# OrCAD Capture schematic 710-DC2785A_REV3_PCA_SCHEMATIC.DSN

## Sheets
1 PAGE3: size A
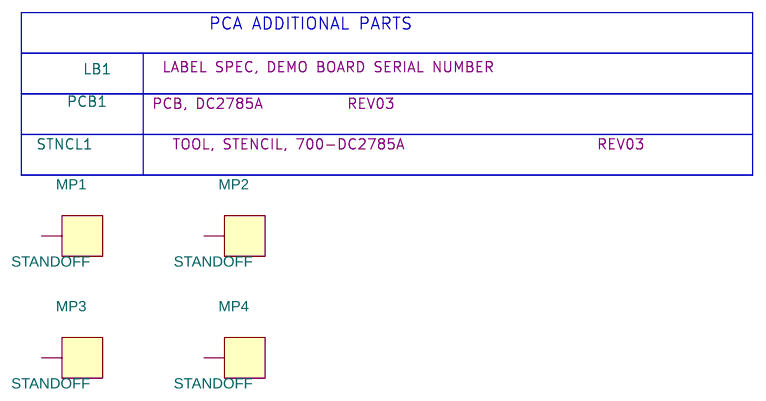
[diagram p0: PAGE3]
2 PAGE1: size Custom; company: ANALOG DEVICES INC.; note: DEMO BOARD BILL OF MATERIALS; note: TINY QUAD STEP-DOWN     MODULE     REGULATOR
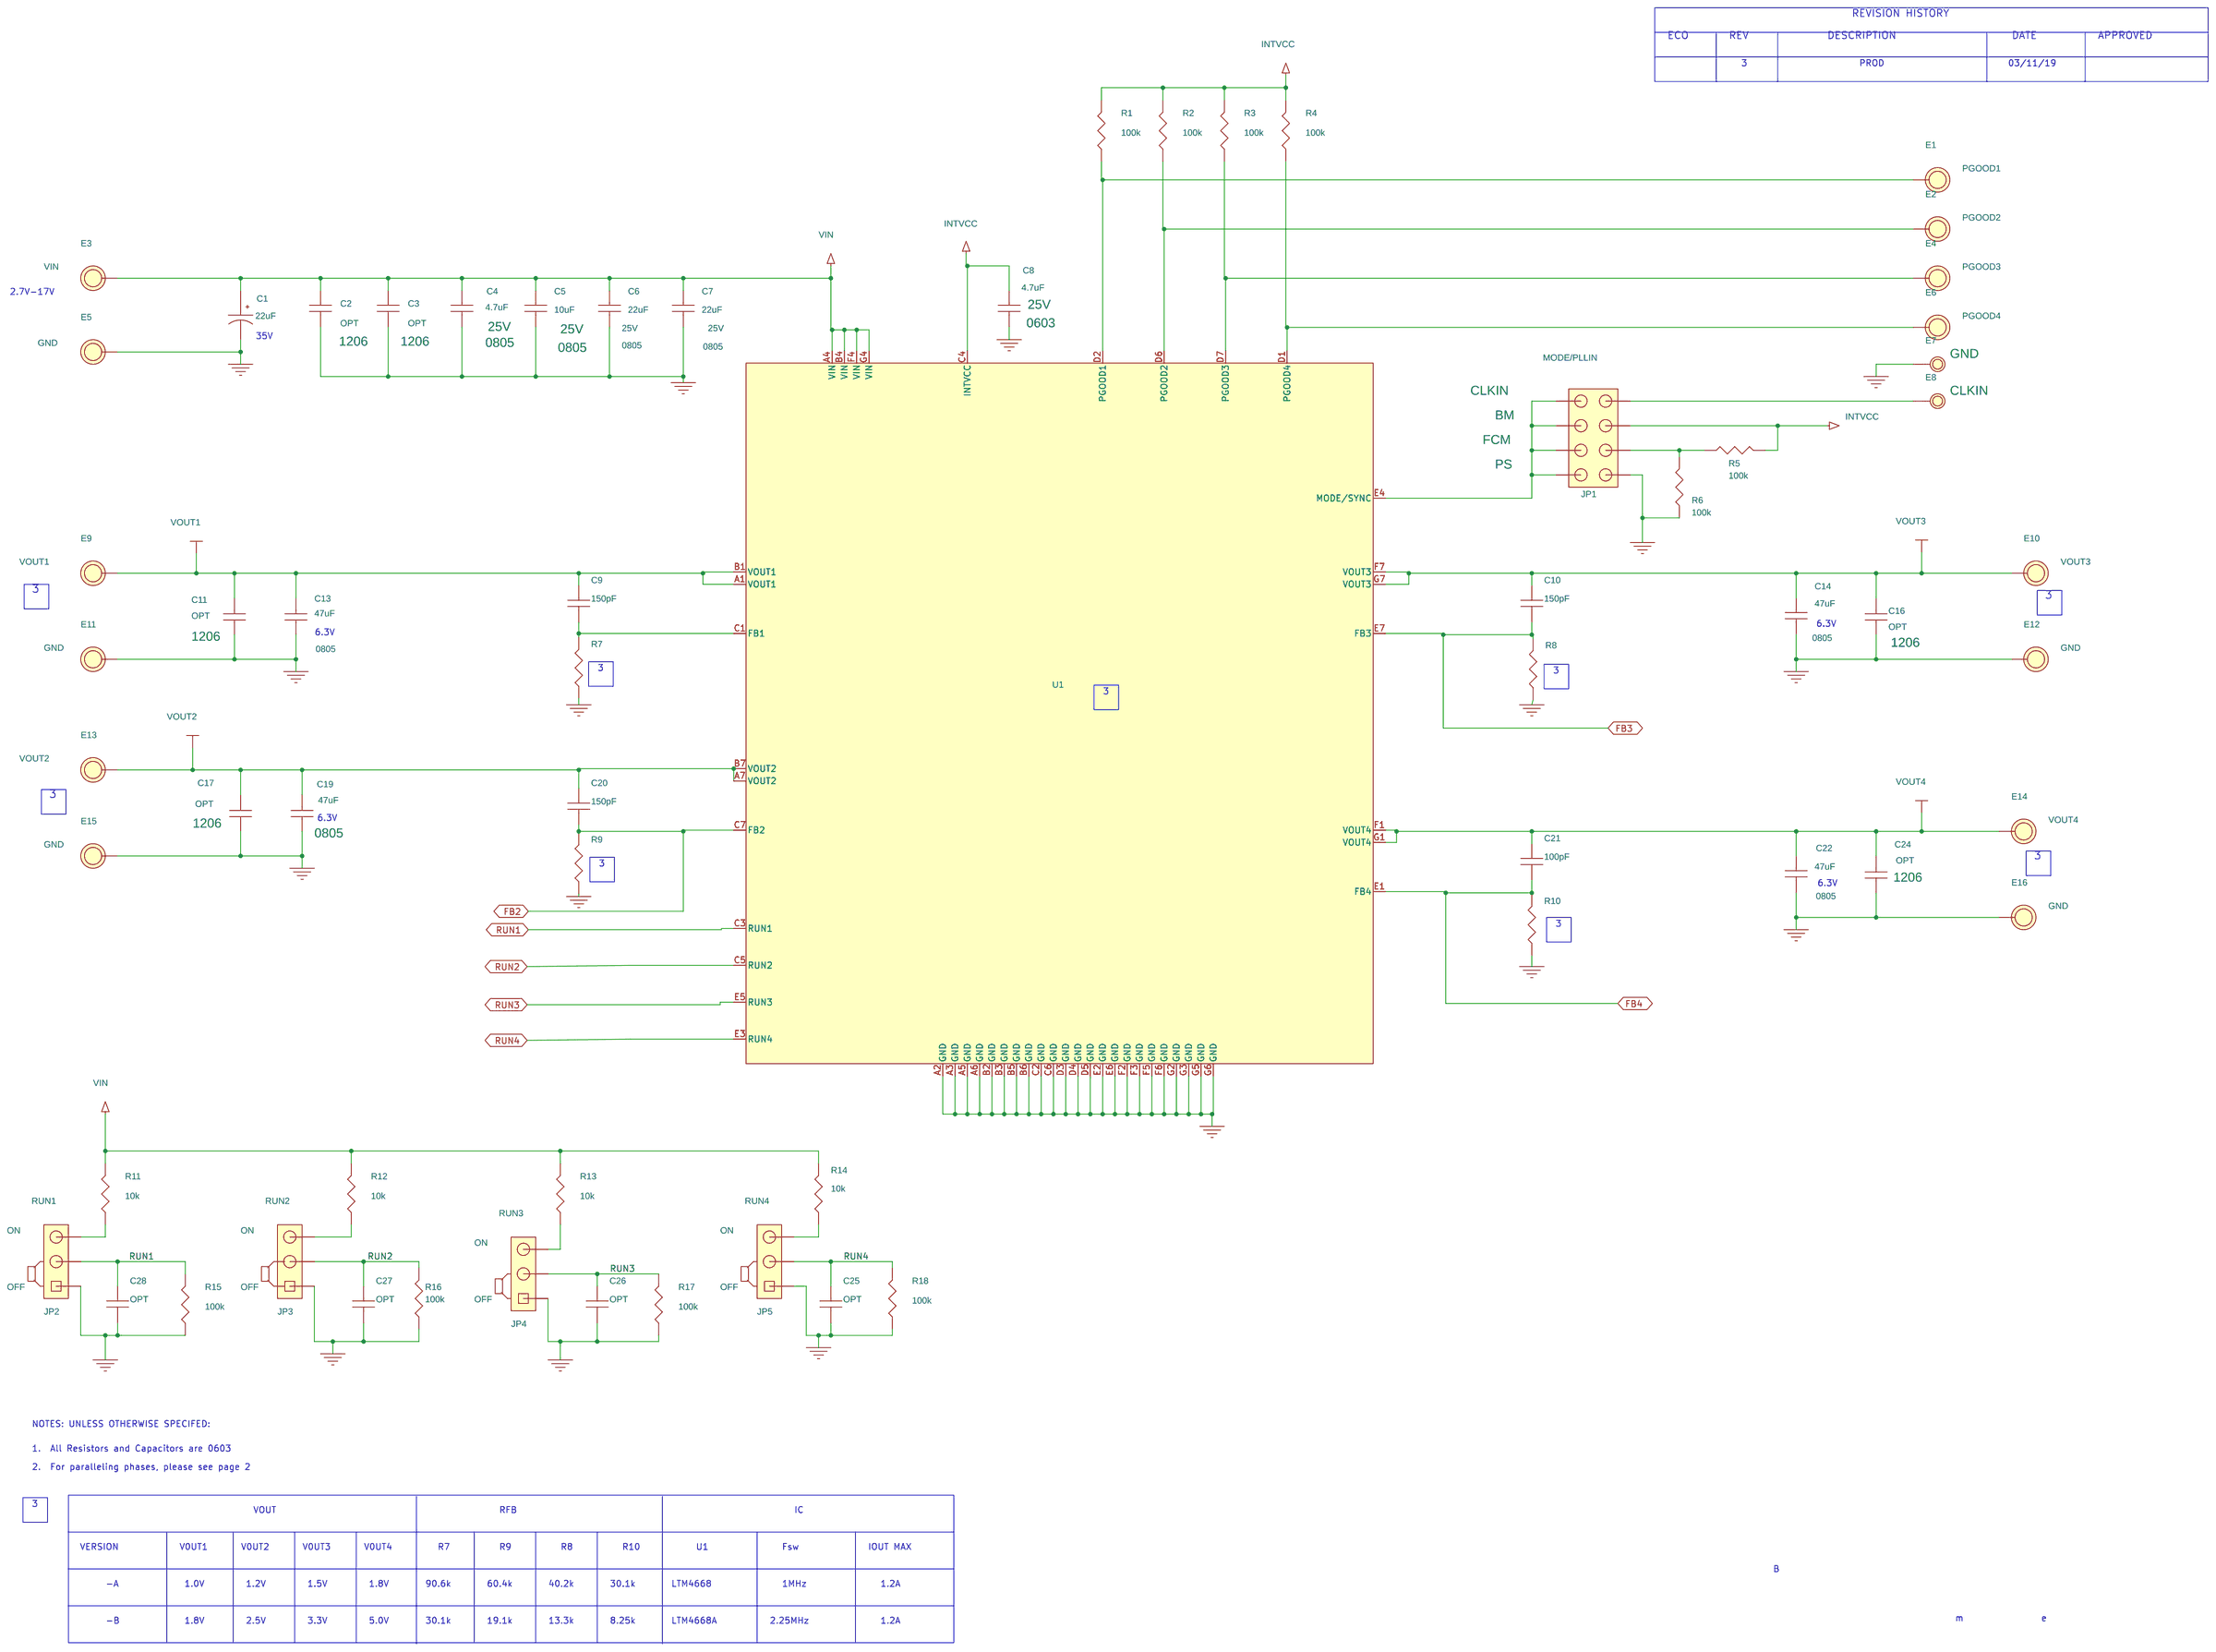
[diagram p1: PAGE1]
3 PAGE2: size Custom; company: ANALOG DEVICES INC.; note: DEMO BOARD BILL OF MATERIALS; note: TINY QUAD STEP-DOWN     MODULE     REGULATOR
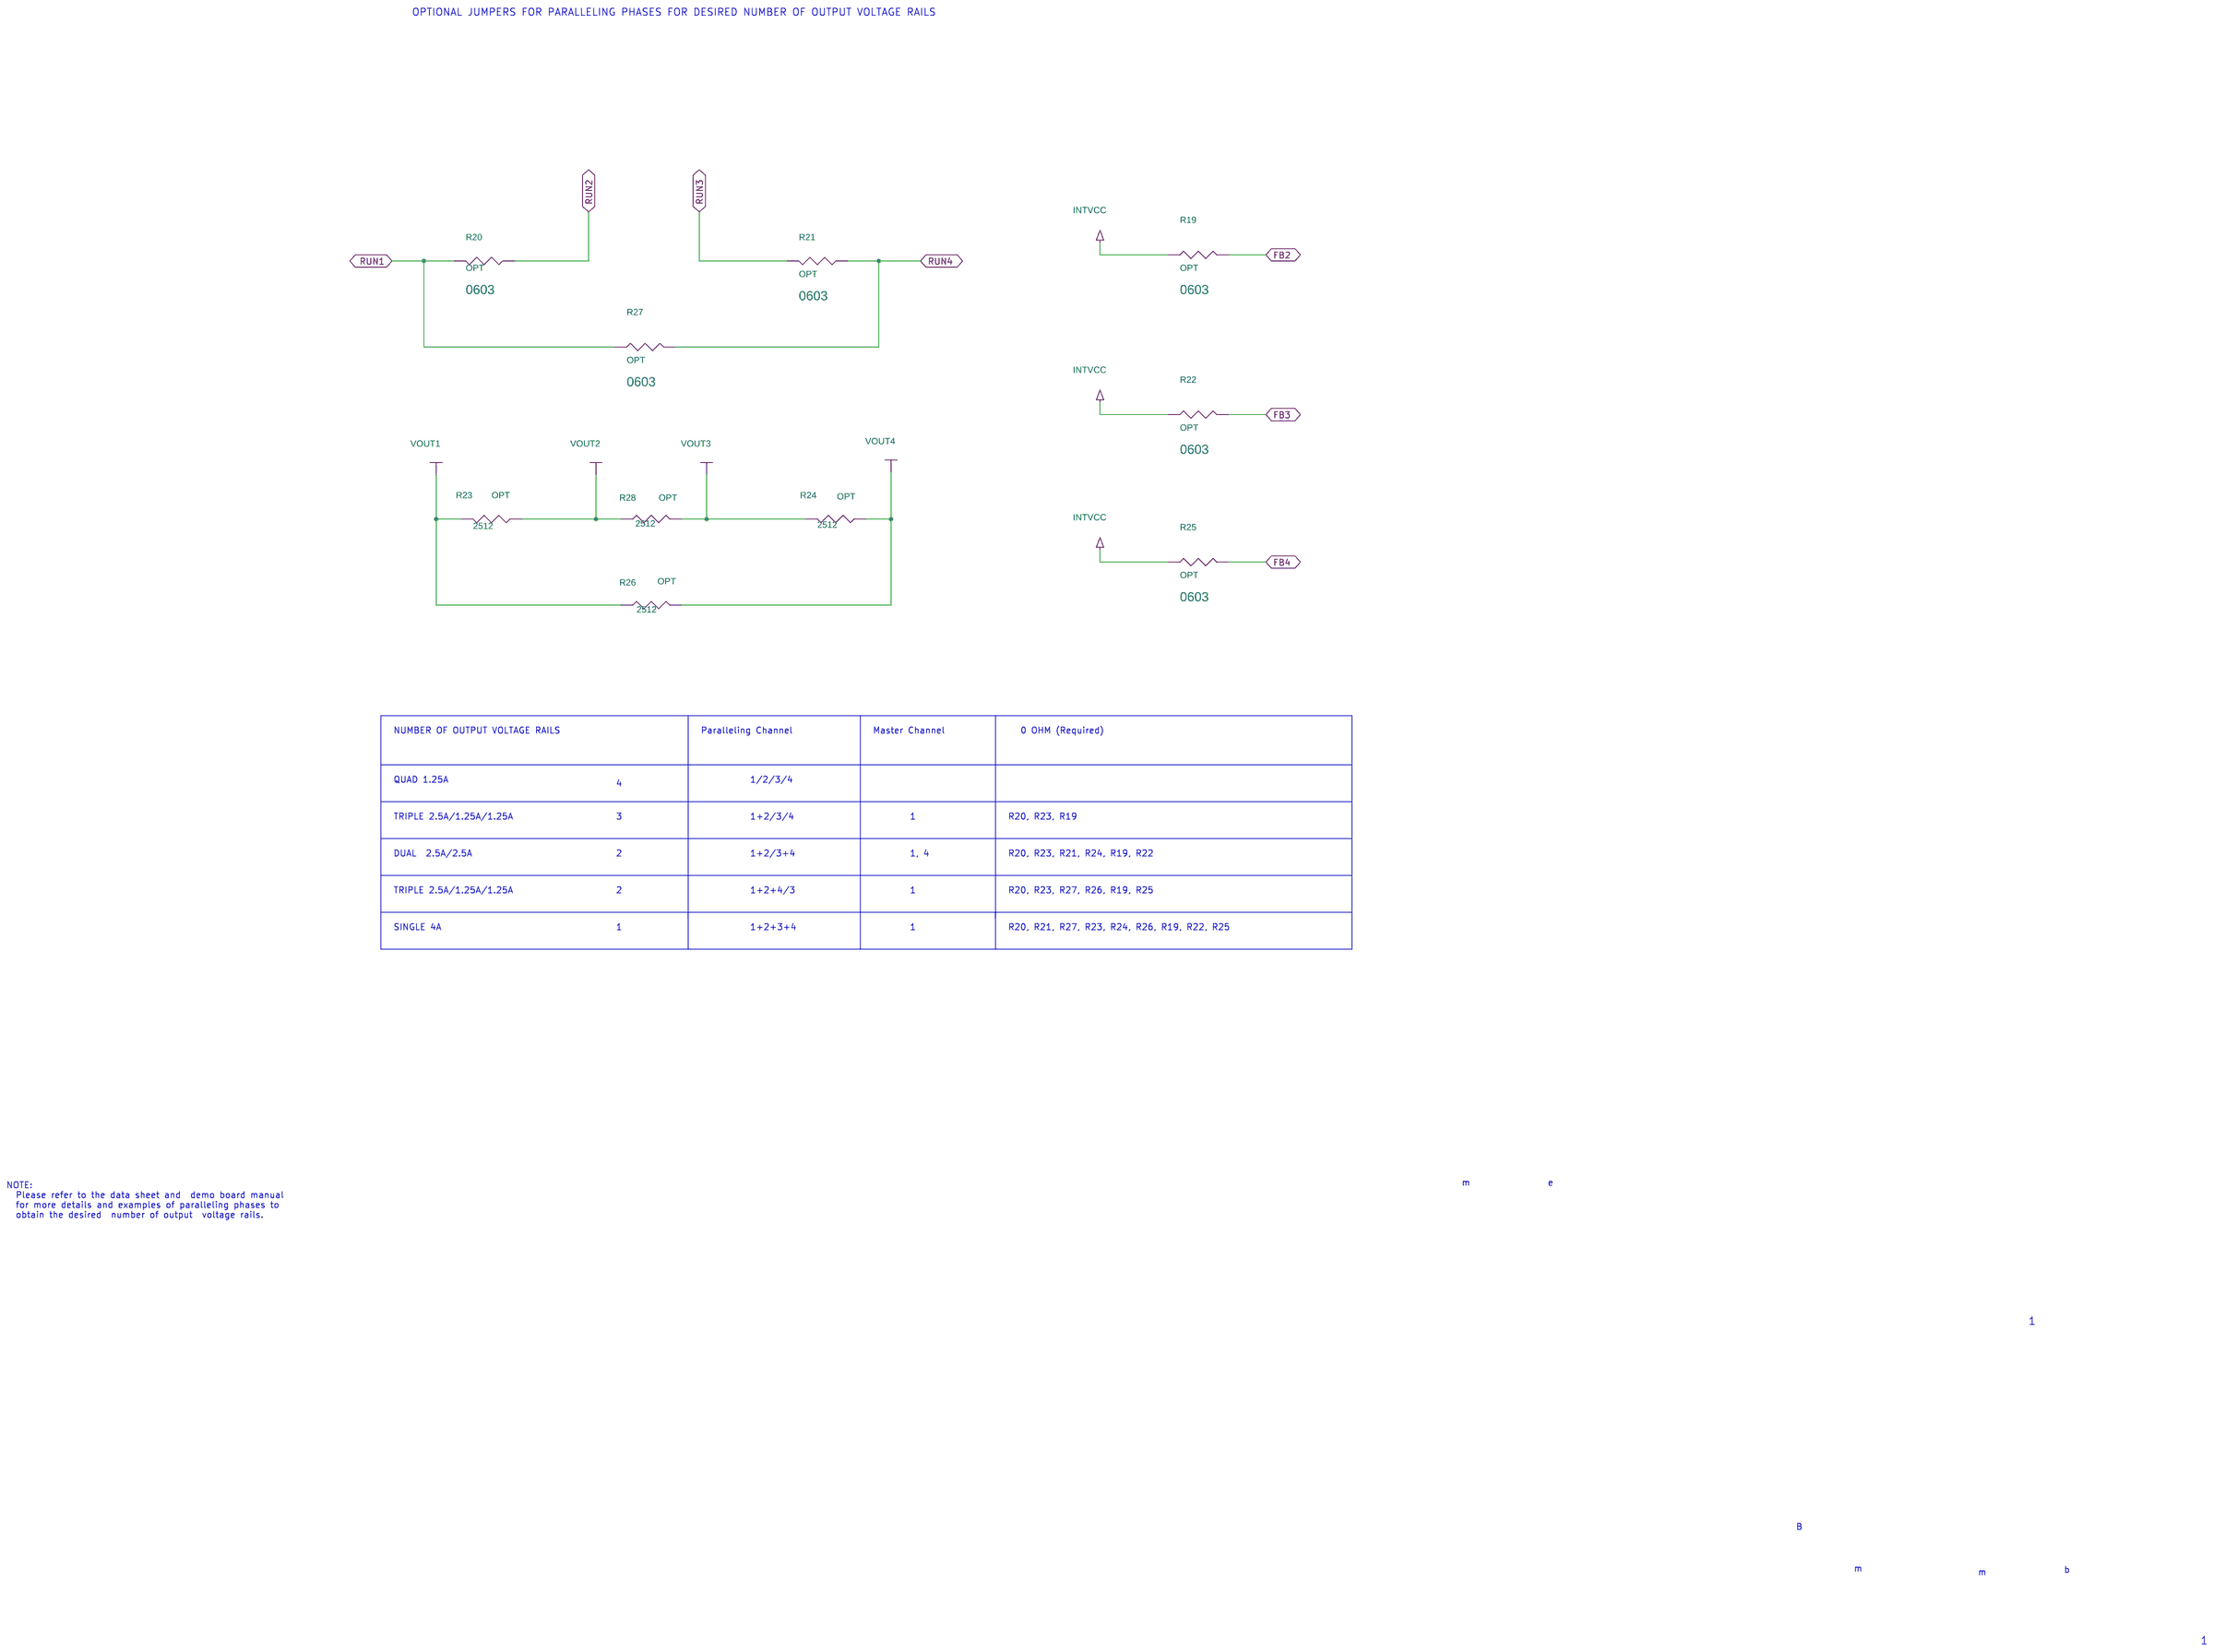
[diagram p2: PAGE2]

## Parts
sheet PAGE1
C1  22uF  [CAPMP7343N]
C2  OPT  [CC1206N]
C3  OPT  [CC1206N]
C4  4.7uF  [CC0805N]
C5  10uF  [CC0805N]
C6  22uF  [CC0805N]
C7  22uF  [CC0805N]
C8  4.7uF  [CC0603N]
C9  150pF  [CC0603N]
C10  150pF  [CC0603N]
C11  OPT  [CC1206N]
C13  47uF  [CC0805N]
C14  47uF  [CC0805N]
C16  OPT  [CC1206N]
C17  OPT  [CC1206N]
C19  47uF  [CC0805N]
C20  150pF  [CC0603N]
C21  100pF  [CC0603N]
C22  47uF  [CC0805N]
C24  OPT  [CC1206N]
C25  OPT  [CC0603N]
C26  OPT  [CC0603N]
C27  OPT  [CC0603N]
C28  OPT  [CC0603N]
E1  TEST POINT  [MILLMAX2501]
E2  TEST POINT  [MILLMAX2501]
E3  TEST POINT  [MILLMAX2501]
E4  TEST POINT  [MILLMAX2501]
E5  TEST POINT  [MILLMAX2501]
E6  TEST POINT  [MILLMAX2501]
E7  TEST POINT  [MILLMAX2308]
E8  TEST POINT  [MILLMAX2308]
E9  TEST POINT  [MILLMAX2501]
E10  TEST POINT  [MILLMAX2501]
E11  TEST POINT  [MILLMAX2501]
E12  TEST POINT  [MILLMAX2501]
E13  TEST POINT  [MILLMAX2501]
E14  TEST POINT  [MILLMAX2501]
E15  TEST POINT  [MILLMAX2501]
E16  TEST POINT  [MILLMAX2501]
JP1  HDR  [HD2X4-079]
JP2  HDR  [HD1X3-079]
JP3  HDR  [HD1X3-079]
JP4  HDR  [HD1X3-079]
JP5  HDR  [HD1X3-079]
R1  100k  [CR0603N]
R2  100k  [CR0603N]
R3  100k  [CR0603N]
R4  100k  [CR0603N]
R5  100k  [CR0603N]
R6  100k  [CR0603N]
R7  60.4k  [CR0603N]
R8  30.1k  [CR0603N]
R9  40.2k  [CR0603N]
R10  19.1k  [CR0603N]
R11  10k  [CR0603N]
R12  10k  [CR0603N]
R13  10k  [CR0603N]
R14  10k  [CR0603N]
R15  100k  [CR0603N]
R16  100k  [CR0603N]
R17  100k  [CR0603N]
R18  100k  [CR0603N]
U1  LTM4668-BGA  [LTC-BGA-49-1518]
XJP1  SHUNT
XJP2  SHUNT
XJP3  SHUNT
XJP4  SHUNT
XJP5  SHUNT
sheet PAGE2
R19  OPT  [CR0603N]
R20  OPT  [CR0603N]
R21  OPT  [CR0603N]
R22  OPT  [CR0603N]
R23  OPT  [CR2512N]
R24  OPT  [CR2512N]
R25  OPT  [CR0603N]
R26  OPT  [CR2512N]
R27  OPT  [CR0603N]
R28  OPT  [CR2512N]
sheet PAGE3
LB1  LABEL  [895-0154_REV01]
MP1  STANDOFF  [KEYSTONE_8829-8834]
MP2  STANDOFF  [KEYSTONE_8829-8834]
MP3  STANDOFF  [KEYSTONE_8829-8834]
MP4  STANDOFF  [KEYSTONE_8829-8834]
PCB1  PCB, DC2785A
STNCL1  TOOL, STENCIL, 700-DC2785A

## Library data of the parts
C1 = CAP_P: CAP.,22uF,TANT.,35V,20%,7343,TPSE, NO SUBS. ALLOWED; CLASS: DISCRETE; Dielectric Type: TANT.; FPLIST: CAPMP7343N,CAMP7343L,CAMP7343M; Manufacturer: AVX; Manufacturer PN: TPSE226M035R0125; PART_NUMBER: 150-0636; Package Size: 7343; Package Type: Surface Mount; Part Number: AVX TPSE226M035R0125; Rated Voltage: 35V; Tolerance: 20%; UserField01: NO SUB ALLOW
C2 C3 C11 C17 C24 = CAP: CAP., OPTION, 1206; CLASS: DISCRETE; FPLIST: CC1206N,CC1206L,CC1206M; PART_NUMBER: 150-3160; Package Size: 1206; Package Type: SMD; Part Number: OPTION
C4 = CAP: CAP.,4.7uF,X7R,25V,10%,0805; CLASS: DISCRETE; Dielectric Type: X7R; FPLIST: CC0805N,CC0805L,CC0805M; Manufacturer: MURATA; Manufacturer PN: GRM21BR71E475KA73L; PART_NUMBER: 150-3337; Package Size: 0805; Part Number: MURATA GRM21BR71E475KA73L; Rated Voltage: 25V; Tolerance: 10%
C5 = CAP: CAP.,10uF,X5R,25V,10%,0805; CLASS: DISCRETE; Dielectric Type: X5R; FPLIST: CC0805N,CC0805L,CC0805M; Manufacturer: MURATA; Manufacturer PN: GRM219R61E106KA12D; PART_NUMBER: 150-3455; Package Size: 0805; Part Number: MURATA GRM219R61E106KA12D; Rated Voltage: 25V; Tolerance: 10%; UserField01: Thickness = 0.85 +/-0.1mm
C6 C7 = CAP: CAP.,22uF,X5R,25V,20%,0805; CLASS: DISCRETE; Dielectric Type: X5R; FPLIST: CC0805N,CC0805L,CC0805M; Manufacturer: MURATA; Manufacturer PN: GRM21BR61E226ME44L; PART_NUMBER: 150-0387; Package Size: 0805; Part Number: MURATA GRM21BR61E226ME44L; Rated Voltage: 25V; Tolerance: 20%
C8 = CAP: CAP.,4.7uF,X5R,25V,20%,0603; 1ST PART FIELD: 25V; CLASS: DISCRETE; Dielectric Type: X5R; FPLIST: CC0603N,CC0603L,CC0603M; Manufacturer: TDK; Manufacturer PN: C1608X5R1E475M080AC; PART_NUMBER: 150-2378; Package Size: 0603; Part Number: TDK C1608X5R1E475M080AC; Rated Voltage: 25V; Tolerance: 20%
C9 C10 C20 = CAP: CAP.,150pF,NP0,50V,5%,0603; 1ST PART FIELD: 25V; 2ND PART FIELD: 0805-1206; CLASS: DISCRETE; Dielectric Type: NP0; FPLIST: CC0603N,CC0603L,CC0603M; Manufacturer: AVX; Manufacturer PN: 06035A151JAT2A; PART_NUMBER: 150-2306; Package Size: 0603; Part Number: AVX 06035A151JAT2A; Rated Voltage: 50V; Tolerance: 5%
C13 C14 C19 C22 = CAP: CAP.,47uF,X5R,6.3V,20%,0805; 1ST PART FIELD: 6.3V; CLASS: DISCRETE; Dielectric Type: X5R; FPLIST: CC0805N,CC0805L,CC0805M; Inventory Qty: 15642; Manufacturer: MURATA; Manufacturer PN: GRM21BR60J476ME15L; PART_NUMBER: 150-0140; Package Size: 0805; Part Number: TDK C3216X5R1C476M160AB; Rated Voltage: 6.3V; Tolerance: 20%
C16 = CAP: CAP., OPTION, 1206; 1ST PART FIELD: 25V; 2ND PART FIELD: 0805-1206; CLASS: DISCRETE; PART_NUMBER: 150-3160; Package Size: 1206; Package Type: SMD; Part Number: OPTION
C21 = CAP: CAP.,100pF,C0G,50V,5%,0603,AEC-Q200; 1ST PART FIELD: 25V; 2ND PART FIELD: 0805-1206; CLASS: DISCRETE; Dielectric Type: C0G; FPLIST: CC0603N,CC0603L,CC0603M; Manufacturer: TDK; Manufacturer PN: CGA3E2C0G1H101J080AA; PART_NUMBER: 150-0516; Package Size: 0603; Part Number: TDK CGA3E2C0G1H101J080AA; Rated Voltage: 50V; Tolerance: 5%; UserField01: AEC-Q200
C25-C28 = CAP: CAP., OPTION, 0603; 1ST PART FIELD: 25V; 2ND PART FIELD: 0805-1206; CLASS: DISCRETE; FPLIST: CC0603N,CC0603L,CC0603M; PART_NUMBER: 150-3038; Package Size: 0603; Package Type: SMD; Part Number: OPTION; UserField01: OPTION
E1 = TURRET_A: TEST POINT,TURRET,0.094",MTG. HOLE; CLASS: IO; FPLIST: MILLMAX2501,MILLMAX2501_ALT1; Manufacturer: MILL-MAX; Manufacturer PN: 2501-2-00-80-00-00-07-0; PART_FIELD_01: PGOOD1; PART_NUMBER: 260-0003; Part Number: MILL-MAX 2501-2-00-80-00-00-07-0
E2 = TURRET_A: TEST POINT,TURRET,0.094",MTG. HOLE; CLASS: IO; FPLIST: MILLMAX2501,MILLMAX2501_ALT1; Manufacturer: MILL-MAX; Manufacturer PN: 2501-2-00-80-00-00-07-0; PART_FIELD_01: PGOOD2; PART_NUMBER: 260-0003; Part Number: MILL-MAX 2501-2-00-80-00-00-07-0
E3 = TURRET_A: TEST POINT,TURRET,0.094",MTG. HOLE; CLASS: IO; FPLIST: MILLMAX2501,MILLMAX2501_ALT1; Manufacturer: MILL-MAX; Manufacturer PN: 2501-2-00-80-00-00-07-0; PART_FIELD_01: VIN; PART_NUMBER: 260-0003; Part Number: MILL-MAX 2501-2-00-80-00-00-07-0
E4 = TURRET_A: TEST POINT,TURRET,0.094",MTG. HOLE; CLASS: IO; FPLIST: MILLMAX2501,MILLMAX2501_ALT1; Manufacturer: MILL-MAX; Manufacturer PN: 2501-2-00-80-00-00-07-0; PART_FIELD_01: PGOOD3; PART_NUMBER: 260-0003; Part Number: MILL-MAX 2501-2-00-80-00-00-07-0
E5 E11 E12 E15 E16 = TURRET_A: TEST POINT,TURRET,0.094",MTG. HOLE; CLASS: IO; FPLIST: MILLMAX2501,MILLMAX2501_ALT1; Manufacturer: MILL-MAX; Manufacturer PN: 2501-2-00-80-00-00-07-0; PART_FIELD_01: GND; PART_NUMBER: 260-0003; Part Number: MILL-MAX 2501-2-00-80-00-00-07-0
E6 = TURRET_A: TEST POINT,TURRET,0.094",MTG. HOLE; CLASS: IO; FPLIST: MILLMAX2501,MILLMAX2501_ALT1; Manufacturer: MILL-MAX; Manufacturer PN: 2501-2-00-80-00-00-07-0; PART_FIELD_01: PGOOD4; PART_NUMBER: 260-0003; Part Number: MILL-MAX 2501-2-00-80-00-00-07-0
E7 = TEST_POINT_.156_MILL-MAX_2308_A: TEST POINT,TURRET,0.064",MTG. HOLE; CLASS: IO; Manufacturer: MILL-MAX; Manufacturer PN: 2308-2-00-80-00-00-07-0; PART_FIELD_01: GND; PART_NUMBER: 260-0004; Part Number: MILL-MAX 2501-2-00-80-00-00-07-0
E8 = TEST_POINT_.156_MILL-MAX_2308_A: TEST POINT,TURRET,0.064",MTG. HOLE; CLASS: IO; Manufacturer: MILL-MAX; Manufacturer PN: 2308-2-00-80-00-00-07-0; PART_FIELD_01: CLKIN; PART_NUMBER: 260-0004; Part Number: MILL-MAX 2501-2-00-80-00-00-07-0
E9 = TURRET_A: TEST POINT,TURRET,0.094",MTG. HOLE; CLASS: IO; FPLIST: MILLMAX2501,MILLMAX2501_ALT1; Manufacturer: MILL-MAX; Manufacturer PN: 2501-2-00-80-00-00-07-0; PART_FIELD_01: VOUT1; PART_NUMBER: 260-0003; Part Number: MILL-MAX 2501-2-00-80-00-00-07-0
E10 = TURRET_A: TEST POINT,TURRET,0.094",MTG. HOLE; CLASS: IO; FPLIST: MILLMAX2501,MILLMAX2501_ALT1; Manufacturer: MILL-MAX; Manufacturer PN: 2501-2-00-80-00-00-07-0; PART_FIELD_01: VOUT3; PART_NUMBER: 260-0003; Part Number: MILL-MAX 2501-2-00-80-00-00-07-0
E13 = TURRET_A: TEST POINT,TURRET,0.094",MTG. HOLE; CLASS: IO; FPLIST: MILLMAX2501,MILLMAX2501_ALT1; Manufacturer: MILL-MAX; Manufacturer PN: 2501-2-00-80-00-00-07-0; PART_FIELD_01: VOUT2; PART_NUMBER: 260-0003; Part Number: MILL-MAX 2501-2-00-80-00-00-07-0
E14 = TURRET_A: TEST POINT,TURRET,0.094",MTG. HOLE; CLASS: IO; FPLIST: MILLMAX2501,MILLMAX2501_ALT1; Manufacturer: MILL-MAX; Manufacturer PN: 2501-2-00-80-00-00-07-0; PART_FIELD_01: VOUT4; PART_NUMBER: 260-0003; Part Number: MILL-MAX 2501-2-00-80-00-00-07-0
JP1 = HDR2X4_ALT2: CONN.,HDR,MALE,2x4,2mm,VERT, STR, THT; CLASS: IO; First Part Field: MODE/PLLIN; Manufacturer: SAMTEC; Manufacturer PN: TMM-104-02-L-D; PART_FIELD_02: CLKIN; PART_FIELD_03: BM; PART_FIELD_04: FCM; PART_FIELD_05: PS; PART_NUMBER: 250-0421; Part Number: SAMTEC TMM-104-02-L-D
JP2 = 1X3_B: CONN.,HDR,MALE,1x3,2mm,STR, THT,NO SUBS. ALLOWED; 11th Part Field: ON; 12th Part Field: RUN1; 9th Part Field: OFF; CLASS: IO; Manufacturer: Wurth Elektronik; Manufacturer PN: 62000311121; PART_NUMBER: 250-0639; Part Number: Wurth Elektronik 62000311121
JP3 = 1X3_B: CONN.,HDR,MALE,1x3,2mm,STR, THT,NO SUBS. ALLOWED; 11th Part Field: ON; 12th Part Field: RUN2; 9th Part Field: OFF; CLASS: IO; Manufacturer: Wurth Elektronik; Manufacturer PN: 62000311121; PART_NUMBER: 250-0639; Part Number: Wurth Elektronik 62000311121
JP4 = 1X3_B: CONN.,HDR,MALE,1x3,2mm,STR, THT,NO SUBS. ALLOWED; 11th Part Field: ON; 12th Part Field: RUN3; 9th Part Field: OFF; CLASS: IO; Manufacturer: Wurth Elektronik; Manufacturer PN: 62000311121; PART_NUMBER: 250-0639; Part Number: Wurth Elektronik 62000311121
JP5 = 1X3_B: CONN.,HDR,MALE,1x3,2mm,STR, THT,NO SUBS. ALLOWED; 11th Part Field: ON; 12th Part Field: RUN4; 9th Part Field: OFF; CLASS: IO; Manufacturer: Wurth Elektronik; Manufacturer PN: 62000311121; PART_NUMBER: 250-0639; Part Number: Wurth Elektronik 62000311121
R1-R4 = RES: RES.,100k OHMS,5%,1/10W,0603; CLASS: DISCRETE; FPLIST: CR0603N,CR0603L,CR0603M; Manufacturer: PANASONIC; Manufacturer PN: ERJ3GEYJ104V; PART_NUMBER: 100-0061; Package Size: 0603; Part Number: PANASONIC ERJ3GEYJ104V; Rated Power: 1/10W; Temperature Coefficient: 200ppm/C; Tolerance: 5%
R5 R6 R15-R18 = RES: RES.,100k OHMS,1%,1/10W,0603; CLASS: DISCRETE; FPLIST: CR0603N,CR0603L,CR0603M; Manufacturer: VISHAY; Manufacturer PN: CRCW0603100KFKEA; PART_NUMBER: 100-0343; Package Size: 0603; Part Number: VISHAY CRCW0603100KFKEA; Rated Power: 1/10W; Temperature Coefficient: +/-100ppm; Tolerance: 1%
R7 = RES: RES.,AEC-Q200,60.4k OHMS,1%,1/10W,0603; CLASS: DISCRETE; FPLIST: CR0603N,CR0603L,CR0603M; Manufacturer: VISHAY; Manufacturer PN: CRCW060360K4FKEA; PART_NUMBER: 100-2367; Package Size: 0603; Part Number: VISHAY CRCW060360K4FKEA; Rated Power: 1/10W; Temperature Coefficient: 100ppm/C; Tolerance: 1%
R8 = RES: RES.,AEC-Q200,30.1k OHMS,1%,1/10W,0603; CLASS: DISCRETE; FPLIST: CR0603N,CR0603L,CR0603M; Manufacturer: VISHAY; Manufacturer PN: CRCW060330K1FKEA; PART_NUMBER: 100-2524; Package Size: 0603; Part Number: VISHAY CRCW060330K1FKEA; Rated Power: 1/10W; Temperature Coefficient: 100ppm/C; Tolerance: 1%
R9 = RES: RES.,AEC-Q200,40.2k OHMS,1%,1/10W,0603; CLASS: DISCRETE; FPLIST: CR0603N,CR0603L,CR0603M; Manufacturer: VISHAY; Manufacturer PN: CRCW060340K2FKEA; PART_NUMBER: 100-2431; Package Size: 0603; Part Number: VISHAY CRCW060340K2FKEA; Rated Power: 1/10W; Temperature Coefficient: 100ppm/C; Tolerance: 1%
R10 = RES: RES.,AEC-Q200,19.1k OHMS,1%,1/10W,0603; CLASS: DISCRETE; FPLIST: CR0603N,CR0603L,CR0603M; Manufacturer: PANASONIC; Manufacturer PN: ERJ3EKF1912V; PART_NUMBER: 100-0270; Package Size: 0603; Part Number: VISHAY CRCW060319K1FKEA; Rated Power: 1/10W; Temperature Coefficient: 100ppm/C; Tolerance: 1%
R11-R14 = RES: RES.,AEC-Q200,10k OHMS,1%,1/10W,0603; CLASS: DISCRETE; FPLIST: CR0603N,CR0603L,CR0603M; Manufacturer: VISHAY; Manufacturer PN: CRCW060310K0FKEA; PART_NUMBER: 100-2012; Package Size: 0603; Part Number: VISHAY CRCW060310K0FKEA; Rated Power: 1/10W; Temperature Coefficient: +/-100ppm/C; Tolerance: 1%
U1 = LTM4668-BGA: IC,Quad DC/DC 1A uModule Reg.,49-pins BGA; CLASS: IC; Manufacturer: LINEAR TECH.; Manufacturer PN: LTM4668EY#PBF; PART_NUMBER: LTM4668EY#PBF; Package Size: 6.25X6.25X2.1mm; Package Type: 49-pins BGA; Part Number: LINEAR TECH. LTM4668EY#PBF
XJP1 = SHUNT_2MM_C: CONN.,SHUNT,FEMALE,2 POS,2mm; CLASS: IO; Manufacturer: Wurth Elektronik; Manufacturer PN: 60800213421; PART_NUMBER: 250-0485; Part Number: Wurth Elektronik 60800213421
XJP2-XJP5 = SHUNT_2MM: CONN.,SHUNT,FEMALE,2 POS,2mm; CLASS: IO; Manufacturer: Wurth Elektronik; Manufacturer PN: 60800213421; PART_NUMBER: 250-0485; Part Number: Wurth Elektronik 60800213421
R19-R22 R25 R27 = RES: RES., OPTION, 0603; CLASS: DISCRETE; FPLIST: CR0603N,CR0603L,CR0603M; PART_NUMBER: 100-2374; Package Size: 0603; Part Number: OPTION
R23 R24 R26 R28 = RES: RES., OPTION, 2512; CLASS: DISCRETE; FPLIST: CR2512N,CR2512L,CR2512M,USER_ASSIGNED; PART_NUMBER: 100-2376; Package Size: 2512; Part Number: OPTION
LB1 = BLANK_LABEL: LABEL SPEC, DEMO BOARD SERIAL NUMBER; Manufacturer: BRADY; Manufacturer PN: THT-96-717-10; PART_NUMBER: 895-0154
MP1-MP4 = MP-PINNED: STANDOFF,NYLON,SNAP-ON,0.25" (6.4mm); CLASS: MECHANICAL PART; Manufacturer: KEYSTONE; Manufacturer PN: 8831; PART_NUMBER: 763-0006
PCB1 = BLANK_PCB_PART: BOM Notes: REV03; CLASS: DISCRETE; Manufacturer: EAGLE ELECTRONICS INC.; Manufacturer PN: 600-DC2785A; PART_NUMBER: 600-DC2785A
STNCL1 = BLANK_STENCIL_PART: BOM Notes: REV03; CLASS: DISCRETE; Manufacturer: LINEAR TECH.; Manufacturer PN: 830-DC2785A; PART_NUMBER: 830-DC2785A

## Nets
GND: C1.2 C2.2 C3.2 C4.2 C5.2 C6.2 C7.2 C8.2 C11.1 C13.1 C14.2 C16.1 C17.1 C19.1 C22.2 C24.1 C25.2 C26.2 C27.2 C28.2 E5.1 E7.1 E11.1 E12.1 E15.1 E16.1 JP1.7 JP2.1 JP3.1 JP4.1 JP5.1 R6.1 R7.1 R8.1 R9.1 R10.1 R15.1 R16.1 R17.1 R18.1 U1.A2(GND) U1.A3(GND) U1.A5(GND) U1.A6(GND) U1.B2(GND) U1.B3(GND) U1.B5(GND) U1.B6(GND) U1.C2(GND) U1.C6(GND) U1.D3(GND) U1.D4(GND) U1.D5(GND) U1.E2(GND) U1.E6(GND) U1.F2(GND) U1.F3(GND) U1.F5(GND) U1.F6(GND) U1.G2(GND) U1.G3(GND) U1.G5(GND) U1.G6(GND)
VIN: C1.1 C2.1 C3.1 C4.1 C5.1 C6.1 C7.1 E3.1 R11.2 R12.2 R13.2 R14.2 U1.A4(VIN) U1.B4(VIN) U1.F4(VIN) U1.G4(VIN)
FB2: C20.2 R9.2 R19.2 U1.C7(FB2)
FB3: C10.2 R8.2 R22.2 U1.E7(FB3)
FB4: C21.2 R10.2 R25.2 U1.E1(FB4)
INTVCC: C8.1 JP1.3 R1.2 R2.2 R3.2 R4.2 R5.2 R19.1 R22.1 R25.1 U1.C4(INTVCC)
RUN1: C28.1 JP2.2 R15.2 R20.2 R27.1 U1.C3(RUN1)
RUN2: C27.1 JP3.2 R16.2 R20.1 U1.C5(RUN2)
RUN3: C26.1 JP4.2 R17.2 R21.2 U1.E5(RUN3)
RUN4: C25.1 JP5.2 R18.2 R21.1 R27.2 U1.E3(RUN4)
VOUT1: C9.1 C11.2 C13.2 E9.1 R23.2 R26.1 U1.A1(VOUT1) U1.B1(VOUT1)
VOUT2: C17.2 C19.2 C20.1 E13.1 R23.1 R28.1 U1.A7(VOUT2) U1.B7(VOUT2)
VOUT3: C10.1 C14.1 C16.2 E10.1 R24.2 R28.2 U1.F7(VOUT3) U1.G7(VOUT3)
VOUT4: C21.1 C22.1 C24.2 E14.1 R24.1 R26.2 U1.F1(VOUT4) U1.G1(VOUT4)
N19659293: JP1.2 JP1.4 JP1.6 JP1.8 U1.E4(MODE/SYNC)
N19660260: JP1.5 R5.1 R6.2
N19662265: E8.1 JP1.1
N19899722: C9.2 R7.2 U1.C1(FB1)
N19907684: E6.1 R4.1 U1.D1(PGOOD4)
N19907724: E2.1 R2.1 U1.D6(PGOOD2)
N19907729: E4.1 R3.1 U1.D7(PGOOD3)
N19907975: E1.1 R1.1 U1.D2(PGOOD1)
N19911416: JP4.3 R13.1
N19911419: JP5.3 R14.1
N19988470: JP3.3 R12.1
N19989903: JP2.3 R11.1

Not connected (* = marked no-connect by the designer): MP1 1; MP2 1; MP3 1; MP4 1

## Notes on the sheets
sheet 1
- PCA ADDITIONAL PARTS
sheet 2
- REVISION HISTORY
- ECO
- REV
- DESCRIPTION
- DATE
- APPROVED
- 3
- PROD
- 03/11/19
- 2.7V-17V
- 35V
- 3
- 3
- 6.3V
- 6.3V
- 3
- 3
- 3
- 3
- 6.3V
- 3
- 3
- 6.3V
- 3
- NOTES: UNLESS OTHERWISE SPECIFED:
- 1.  All Resistors and Capacitors are 0603
- 2.  For paralleling phases, please see page 2
- 3
- VOUT
- RFB
- IC
- VERSION
- V0UT1
- V0UT2
- V0UT3
- V0UT4
- R7
- R9
- R8
- R10
- U1
- Fsw
- IOUT MAX
- B
- -A
- 1.0V
- 1.2V
- 1.5V
- 1.8V
- 90.6k
- 60.4k
- 40.2k
- 30.1k
- LTM4668
- 1MHz
- 1.2A
- -B
- 1.8V
- 2.5V
- 3.3V
- 5.0V
- 30.1k
- 19.1k
- 13.3k
- 8.25k
- LTM4668A
- 2.25MHz
- 1.2A
- m
- e
sheet 3
- OPTIONAL JUMPERS FOR PARALLELING PHASES FOR DESIRED NUMBER OF OUTPUT VOLTAGE RAILS
- NUMBER OF OUTPUT VOLTAGE RAILS
- Paralleling Channel
- Master Channel
- 0 OHM (Required)
- QUAD 1.25A
- 1/2/3/4
- 4
- TRIPLE 2.5A/1.25A/1.25A
- 3
- 1+2/3/4
- 1
- R20, R23, R19
- DUAL  2.5A/2.5A
- 2
- 1+2/3+4
- 1, 4
- R20, R23, R21, R24, R19, R22
- TRIPLE 2.5A/1.25A/1.25A
- 2
- 1+2+4/3
- 1
- R20, R23, R27, R26, R19, R25
- SINGLE 4A
- 1
- 1+2+3+4
- 1
- R20, R21, R27, R23, R24, R26, R19, R22, R25
- NOTE:
    Please refer to the data sheet and  demo board manual
    for more details and examples of paralleling phases to
    obtain the desired  number of output  voltage rails.
- m
- e
- 1
- B
- m
- m
- b
- 1
